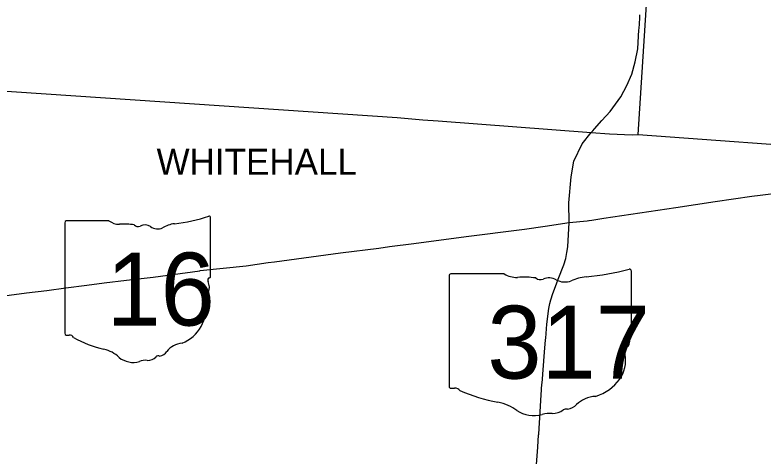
# Model space of a CAD drawing. Extents: x -1146 to -445, y -1283 to -822.
# Drawn here: x -822.31 to -786.59, y -1056.63 to -1035.57 of the extents above; entities that cross this region are included whole.
import ezdxf

# ---------------------------------------------------------------- set-up
doc = ezdxf.new("R2010")
doc.units = 0
for name, color, linetype in [('GM_X_Corporation_Text', 7, 'Continuous'), ('GM_X_State_Route', 7, 'Continuous'), ('GM_X_State_Shield', 7, 'Continuous'), ('GM_X_Township', 7, 'Continuous')]:
    doc.layers.add(name, color=color, linetype=linetype)

msp = doc.modelspace()

# ---------------------------------------------------------------- linework, layer by layer
at = {"layer": 'GM_X_State_Route'}
for points in [[(-792.474, -1035.708), (-792.465, -1035.568)], [(-792.492, -1035.989), (-792.474, -1035.708)], [(-792.696, -1037.804), (-792.571, -1037.178), (-792.51, -1036.27)], [(-792.51, -1036.27), (-792.506, -1036.214), (-792.492, -1035.989)], [(-794.638, -1041.01), (-794.283, -1040.608), (-793.892, -1040.169), (-793.382, -1039.482), (-793.09, -1038.935), (-792.859, -1038.4), (-792.697, -1037.812), (-792.696, -1037.804)], [(-795.846, -1045.478), (-795.865, -1044.544), (-795.755, -1043.302), (-795.618, -1042.541), (-795.225, -1041.726), (-794.786, -1041.185), (-794.719, -1041.103), (-794.638, -1041.01)], [(-787.129, -1044.223), (-786.719, -1044.164), (-784.71, -1043.915), (-784.571, -1043.898), (-784.172, -1043.864), (-783.501, -1043.806)], [(-790.749, -1044.756), (-788.877, -1044.474), (-787.129, -1044.223)], [(-794.769, -1045.363), (-794.193, -1045.276), (-790.749, -1044.756)], [(-797.972, -1045.795), (-796.994, -1045.659), (-795.846, -1045.478)], [(-796.961, -1050.995), (-796.904, -1050.324), (-796.817, -1049.585), (-796.768, -1049.351), (-796.72, -1049.161), (-796.631, -1048.86), (-796.454, -1048.405), (-796.369, -1048.183), (-796.105, -1047.503), (-796.008, -1047.189), (-795.95, -1046.91), (-795.91, -1046.645), (-795.846, -1045.478)], [(-795.846, -1045.478), (-794.98, -1045.395), (-794.903, -1045.383)], [(-794.903, -1045.383), (-794.892, -1045.382), (-794.769, -1045.363)], [(-810.215, -1047.39), (-809.912, -1047.347), (-808.522, -1047.157), (-806.757, -1046.925), (-804.939, -1046.7), (-804.418, -1046.626), (-803.268, -1046.479), (-800.767, -1046.141), (-798.106, -1045.814), (-797.972, -1045.795)], [(-816.987, -1048.237), (-815.709, -1048.086), (-813.488, -1047.777), (-813.467, -1047.775), (-811.262, -1047.539), (-810.215, -1047.39)], [(-830.348, -1050.11), (-829.516, -1049.991), (-828.669, -1049.885), (-827.982, -1049.684), (-827.873, -1049.668), (-826.066, -1049.414), (-825.231, -1049.296), (-824.637, -1049.213), (-824.453, -1049.186), (-823.621, -1049.067), (-822.586, -1048.939), (-821.759, -1048.836), (-820.793, -1048.717), (-819.872, -1048.593), (-818.884, -1048.461), (-818.043, -1048.362), (-816.988, -1048.237), (-816.987, -1048.237)], [(-797.3, -1055.583), (-797.144, -1053.185), (-797.141, -1053.15), (-797.017, -1051.668), (-796.967, -1051.076), (-796.961, -1050.995)], [(-797.403, -1057.025), (-797.34, -1056.197), (-797.339, -1056.179), (-797.303, -1055.633), (-797.3, -1055.583)]]:
    msp.add_lwpolyline(points, dxfattribs=at)
at = {"layer": 'GM_X_State_Shield'}
for p, q in [((-819.926, -1045.484), (-819.926, -1050.768)), ((-817.819, -1045.393), (-819.857, -1045.393)), ((-812.965, -1048.026), (-812.965, -1045.263)), ((-812.965, -1048.026), (-812.965, -1048.026)), ((-801.576, -1048.019), (-801.576, -1053.302)), ((-798.942, -1047.928), (-801.49, -1047.928)), ((-792.875, -1050.56), (-792.875, -1047.797)), ((-792.876, -1050.56), (-792.875, -1050.56))]:
    msp.add_line(p, q, dxfattribs=at)
for centre, radius, start, end in [((-815.444, -1038.191), 7.382, 275.8445, 288.9065), ((-813.042, -1045.251), 0.0775, 351.8621, 97.738), ((-819.846, -1045.473), 0.0806, 98.1301, 188.1301), ((-817.333, -1044.78), 0.782, 231.6195, 271.1119), ((-817.074, -1048.359), 2.808, 80.4867, 94.9883), ((-814.503, -1047.007), 1.485, 97.3462, 120.7689), ((-816.436, -1045.446), 0.226, 219.7921, 297.1024), ((-816.105, -1046.056), 0.469, 54.4667, 119.1411), ((-815.499, -1045.219), 0.564, 233.8562, 294.8282), ((-813.047, -1048.037), 0.0829, 289.6038, 7.7341), ((-812.983, -1048.229), 0.12, 107.944, 210.337), ((-813.746, -1048.578), 0.72, 340.033, 23.6496), ((-812.687, -1049.183), 0.524, 136.8065, 186.9296), ((-815.031, -1049.534), 1.846, 292.3089, 8.9858), ((-819.845, -1050.779), 0.0814, 171.9584, 258.3066), ((-819.833, -1050.239), 0.621, 267.339, 280.6039), ((-819.706, -1051.072), 0.224, 29.7484, 93.2717), ((-816.879, -1046.326), 5.331, 240.4129, 257.1985), ((-814.252, -1052.251), 1.011, 94.4031, 142.5768), ((-818.469, -1053.141), 1.668, 47.1842, 75.836), ((-815.533, -1051.28), 0.597, 282.8732, 323.2771), ((-816.665, -1051.099), 1.058, 230.7004, 286.2918), ((-815.976, -1051.494), 0.564, 268.777, 315.5493), ((-815.466, -1052.006), 0.159, 65.7517, 132.6484), ((-816.053, -1052.925), 0.87, 85.6951, 111.2099)]:
    msp.add_arc(centre, radius, start, end, dxfattribs=at)
for centre, major_axis, start_param, end_param in [((-795.974, -1040.725), (9.227, 0), 4.814394, 5.042369), ((-792.971, -1047.785), (0.0969, 0), 6.141152, 7.989035), ((-801.476, -1048.007), (0.101, 0), 1.712693, 3.28349), ((-798.335, -1047.314), (0.978, 0), 4.042523, 4.731795), ((-798.011, -1050.894), (3.51, 0), 1.404758, 1.657858), ((-794.797, -1049.541), (1.856, 0), 1.699011, 2.107814), ((-797.214, -1047.98), (0.282, 0), 3.836095, 5.185415), ((-796.8, -1048.591), (0.586, 0), 0.950623, 2.079405), ((-796.043, -1047.753), (0.705, 0), 4.081561, 5.145723), ((-792.978, -1050.571), (0.104, 0), 5.05454, 6.418171), ((-792.897, -1050.763), (0.15, 0), 1.883978, 3.671073), ((-793.851, -1051.113), (0.9, 0), 5.934695, 6.695948), ((-792.528, -1051.717), (0.655, 0), 2.387724, 3.262537), ((-795.457, -1052.069), (2.308, 0), 5.101752, 6.440018), ((-801.475, -1053.313), (0.102, 0), 3.00124, 4.508301), ((-801.46, -1052.773), (0.776, 0), 4.665946, 4.897461), ((-801.301, -1053.607), (0.28, 0), 0.519207, 1.627899), ((-797.768, -1048.86), (6.663, 0), 4.195997, 4.488961), ((-794.484, -1054.785), (1.264, 0), 1.647645, 2.488434), ((-799.754, -1055.675), (2.085, 0), 0.823519, 1.323587), ((-797.5, -1053.633), (1.323, 0), 4.026481, 4.996735), ((-796.639, -1054.028), (0.705, 0), 4.691044, 5.507374), ((-796.001, -1054.54), (0.198, 0), 1.147584, 2.315152), ((-796.086, -1053.814), (0.746, 0), 4.937069, 5.64225), ((-796.735, -1055.459), (1.087, 0), 1.495662, 1.94098)]:
    msp.add_ellipse(centre, major_axis=major_axis, ratio=0.8, start_param=start_param, end_param=end_param, dxfattribs=at)
at = {"layer": 'GM_X_Township'}
for points in [[(-792.543, -1041.281), (-791.464, -1024.391), (-791.324, -1021.951), (-791.203, -1019.653), (-791.162, -1018.876), (-791.123, -1018.205), (-791.072, -1017.772), (-790.875, -1015.08), (-790.697, -1011.518), (-790.477, -1007.136), (-790.244, -1003.355)], [(-830.982, -1058.489), (-830.845, -1056.503), (-830.772, -1055.58), (-830.709, -1054.616), (-830.376, -1050.114), (-830.241, -1047.987), (-830.061, -1045.409), (-830.016, -1044.798), (-829.926, -1043.572), (-829.753, -1041.071), (-829.476, -1038.559), (-823.661, -1039.144), (-804.051, -1040.471), (-802.831, -1040.571), (-802.093, -1040.628), (-794.786, -1041.185), (-793.926, -1041.236), (-792.83, -1041.284), (-792.543, -1041.281), (-782.508, -1042.001)]]:
    msp.add_lwpolyline(points, dxfattribs=at)

# ---------------------------------------------------------------- texts
at = {"layer": 'GM_X_Corporation_Text'}
msp.add_text('WHITEHALL', height=1.25, rotation=0, dxfattribs=at).set_placement((-815.546, -1043.2))
at = {"layer": 'GM_X_State_Shield'}
for s, p in [('16', (-817.941, -1050.395)), ('317', (-799.752, -1052.929))]:
    msp.add_text(s, height=3.4805, dxfattribs=at).set_placement(p)

doc.saveas('drawing.dxf')
